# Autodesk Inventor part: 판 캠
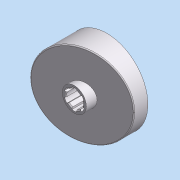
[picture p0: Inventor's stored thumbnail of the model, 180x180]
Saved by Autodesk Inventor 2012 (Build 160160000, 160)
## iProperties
Company: 한국ATC센터
Created: 2012-05
Part Number: 판 캠
Document SubType Name: 모델링
Designer: KYOUNG IL JANG
Mass: 681.586 g
Surface Area: 331.302 cm^2
Volume: 86.8262 cm^3
Density: 7.85 g/cm^3
Material: 강
변환 표준: STEP AP214IS
파일 이름: C:\Users\SeoGD\Desktop\?쒗뿕\??stp
전처리기: Build: 253, Release: 2010 SP1 - Date: Wed 07/29/2009
전송 단위: 밀리미터
불확실성: 0.01
Author: KYOUNG IL JANG
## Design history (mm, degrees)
node "작업 평면4"
sketch "스케치1"
  geometry: C1 r 44.5 at (0, 0); 1 further point
  constraints: 1 centre point, 1 coincident
  dimensions: "d25" = 89 diameter of C1
extrude "돌출1" new body sketch "스케치1" distance "d1" = 40; taper "d2" = 0 deg
sketch "스케치2"
  geometry: L1 (-44.5, 15)-(44.5, 38.847); L2 (-44.5, 0)-(-44.5, 40) reference; L3 (-44.5, 40)-(44.5, 40) reference; L4 (44.5, 0)-(44.5, 40) reference; 1 further point
  constraints: 2 end point, 2 point on line
  dimensions: "d26" = 15 distance of L2.start L1.start; "d27" = 75 deg angle of L1 L2
extrude "돌출2" cut sketch "스케치2" stored distance "d5" = 40; taper "d6" = 0 deg
node "작업 평면1"
sketch "스케치3"
  geometry: C1 r 13 at (0, 0); 1 further point
  constraints: 1 centre point, 1 coincident
  dimensions: "d9" = 26 diameter of C1
extrude "돌출3" join sketch "스케치3" distance "d10" = 38; taper "d11" = 0 deg
hole "구멍1" diameter "d14" = 18; stored, may be unused: countersink angle "d18" = 90 deg, drill point angle "d20" = 118 deg; dims "d12" = 10, "d13" = 10, "d15" = 6, "d16" = 4, "d17" = 2, "d19" = 8
feature "쉘2" dims "d29" = 5
sketch "스케치6"
  geometry: C1 r 17.5 at (0, 0); C2 r 14 at (0, 0) reference; 1 further point
  constraints: 1 centre point, 1 coincident
  dimensions: "d28" = 35 diameter of C1
extrude "돌출4" join sketch "스케치6" stored distance "d30" = 38; taper "d31" = 0 deg
fillet "모깎기1" dims "d32" = 3
chamfer "모따기1" distance "d21" = 1; stored, may be unused: second distance "d22" = 2, angle "d23" = 45 deg
sketch "스케치7"
  geometry: L1 (-12.374, 12.374)-(-27.931, 27.931); A1 r 39.5 centre (0, 0) between (-27.931, 27.931) and (0, 39.5) reference; 2 further points
  constraints: 2 end point, 2 point on circle, 1 point on line, 1 vertical alignment, 2 other
  dimensions: "d33" = 45 deg dimension on point (0, 0) L1.start A1.end
feature "리브1" sketch "스케치7" dims "d34" = 5, "d35" = 1, "d36" = 0
fillet "모깎기2" dims "d37" = 3
sketch "스케치8"
  geometry: L1 (2.5, 10.712)-(2.5, 8.646); L2 (-2.5, 10.712)-(-2.5, 8.646); A1 r 11 centre (0, 0) between (2.5, 10.712) and (-2.5, 10.712); A2 r 9 centre (0, 0) between (2.5, 8.646) and (-2.5, 8.646) reference; 1 further point
  constraints: 4 end point, 4 point on circle, 2 parallel, 1 centre point, 1 coincident, 1 vertical
  dimensions: "d41" = 22 diameter of A1; "d42" = 5 distance between parallel lines of L1 L2
extrude "돌출5" cut sketch "스케치8" stored distance "d43" = 38; taper "d44" = 0 deg
fillet "모깎기3" dims "d48" = 1
node "솔리드1"
node "솔리드 본체"
node "곡면 본체"
pattern_circular "원형 패턴1" dims angle "d39" = 360 deg
pattern_circular "원형 패턴2" dims angle "d46" = 360 deg
node "솔리드2"
